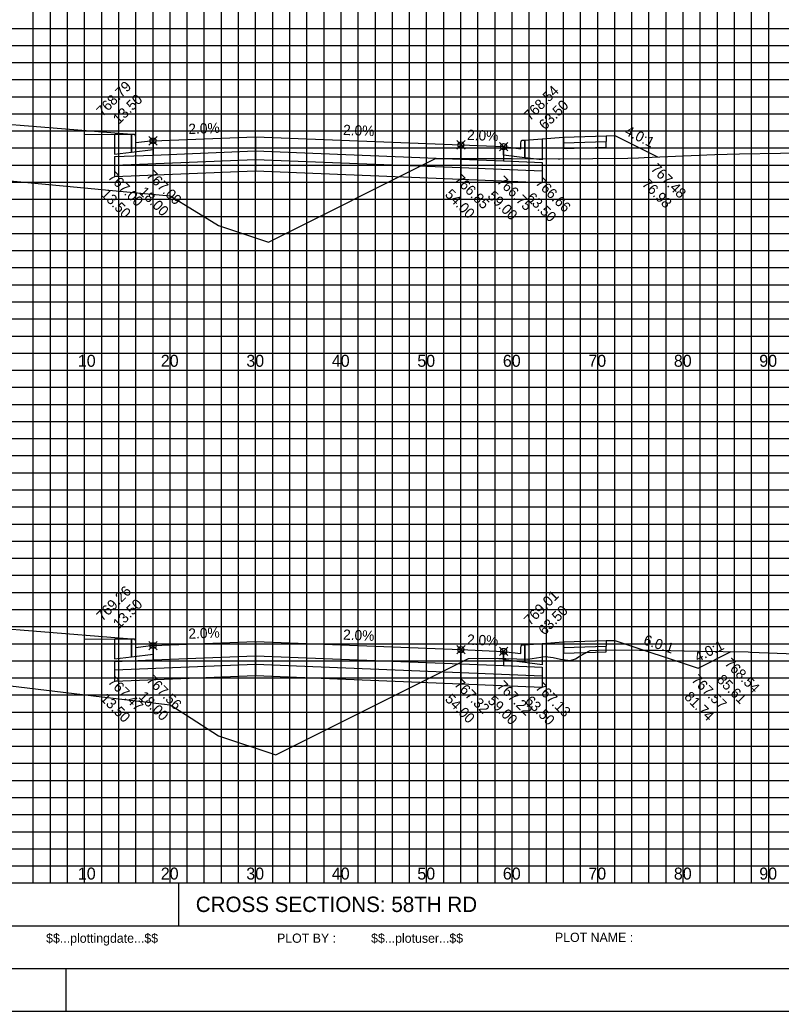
# Model space of a CAD drawing. Extents: x 578243 to 601557, y 174899 to 175559.
# Drawn here: x 600022.3 to 600111.3, y 174898.8 to 175014.8 of the extents above; entities that cross this region are included whole.
import ezdxf

# ---------------------------------------------------------------- set-up
doc = ezdxf.new("R2010")
doc.units = 0
for name, color, linetype in [('E_PROF_Grid', 7, 'Continuous'), ('E_PROF_GridMin', 7, 'Continuous'), ('P_CRDR_Label', 7, 'Continuous'), ('P_CRDR_Link', 7, 'Continuous'), ('P_E_XS_Ground', 7, 'Continuous'), ('P_XS_Text', 7, 'Continuous'), ('PLT_Sheet_Border', 7, 'Continuous'), ('PLT_Sheet_Info', 7, 'Continuous')]:
    doc.layers.add(name, color=color, linetype=linetype)

msp = doc.modelspace()

# ---------------------------------------------------------------- linework, layer by layer
at = {"layer": 'E_PROF_Grid'}
for p, q in [((600029.84, 174913.8), (600029.84, 175108.8)), ((600039.84, 174913.8), (600039.84, 175108.8)), ((600049.84, 174913.8), (600049.84, 175108.8)), ((600059.84, 174913.8), (600059.84, 175108.8)), ((600069.84, 174913.8), (600069.84, 175108.8)), ((600079.84, 174913.8), (600079.84, 175108.8)), ((600089.84, 174913.8), (600089.84, 175108.8)), ((600099.84, 174913.8), (600099.84, 175108.8)), ((600109.84, 174913.8), (600109.84, 175108.8)), ((599869.84, 175013.8), (600184.84, 175013.8)), ((599869.84, 175003.8), (600184.84, 175003.8)), ((599869.84, 174993.8), (600184.84, 174993.8)), ((599869.84, 174983.8), (600184.84, 174983.8)), ((599869.84, 174973.8), (600184.84, 174973.8)), ((599869.84, 174963.8), (600184.84, 174963.8)), ((599869.84, 174953.8), (600184.84, 174953.8)), ((599869.84, 174943.8), (600184.84, 174943.8)), ((599869.84, 174933.8), (600184.84, 174933.8)), ((599869.84, 174923.8), (600184.84, 174923.8))]:
    msp.add_line(p, q, dxfattribs=at)
at = {"layer": 'E_PROF_GridMin'}
for p, q in [((600023.84, 174913.8), (600023.84, 175108.8)), ((600025.84, 174913.8), (600025.84, 175108.8)), ((600027.84, 174913.8), (600027.84, 175108.8)), ((600031.84, 174913.8), (600031.84, 175108.8)), ((600033.84, 174913.8), (600033.84, 175108.8)), ((600035.84, 174913.8), (600035.84, 175108.8)), ((600037.84, 174913.8), (600037.84, 175108.8)), ((600041.84, 174913.8), (600041.84, 175108.8)), ((600043.84, 174913.8), (600043.84, 175108.8)), ((600045.84, 174913.8), (600045.84, 175108.8)), ((600047.84, 174913.8), (600047.84, 175108.8)), ((600051.84, 174913.8), (600051.84, 175108.8)), ((600053.84, 174913.8), (600053.84, 175108.8)), ((600055.84, 174913.8), (600055.84, 175108.8)), ((600057.84, 174913.8), (600057.84, 175108.8)), ((600061.84, 174913.8), (600061.84, 175108.8)), ((600063.84, 174913.8), (600063.84, 175108.8)), ((600065.84, 174913.8), (600065.84, 175108.8)), ((600067.84, 174913.8), (600067.84, 175108.8)), ((600071.84, 174913.8), (600071.84, 175108.8)), ((600073.84, 174913.8), (600073.84, 175108.8)), ((600075.84, 174913.8), (600075.84, 175108.8)), ((600077.84, 174913.8), (600077.84, 175108.8)), ((600081.84, 174913.8), (600081.84, 175108.8)), ((600083.84, 174913.8), (600083.84, 175108.8)), ((600085.84, 174913.8), (600085.84, 175108.8)), ((600087.84, 174913.8), (600087.84, 175108.8)), ((600091.84, 174913.8), (600091.84, 175108.8)), ((600093.84, 174913.8), (600093.84, 175108.8)), ((600095.84, 174913.8), (600095.84, 175108.8)), ((600097.84, 174913.8), (600097.84, 175108.8)), ((600101.84, 174913.8), (600101.84, 175108.8)), ((600103.84, 174913.8), (600103.84, 175108.8)), ((600105.84, 174913.8), (600105.84, 175108.8)), ((600107.84, 174913.8), (600107.84, 175108.8)), ((599869.84, 175011.8), (600184.84, 175011.8)), ((599869.84, 175009.8), (600184.84, 175009.8)), ((599869.84, 175007.8), (600184.84, 175007.8)), ((599869.84, 175005.8), (600184.84, 175005.8)), ((599869.84, 175001.8), (600184.84, 175001.8)), ((599869.84, 174999.8), (600184.84, 174999.8)), ((599869.84, 174997.8), (600184.84, 174997.8)), ((599869.84, 174995.8), (600184.84, 174995.8)), ((599869.84, 174991.8), (600184.84, 174991.8)), ((599869.84, 174989.8), (600184.84, 174989.8)), ((599869.84, 174987.8), (600184.84, 174987.8)), ((599869.84, 174985.8), (600184.84, 174985.8)), ((599869.84, 174981.8), (600184.84, 174981.8)), ((599869.84, 174979.8), (600184.84, 174979.8)), ((599869.84, 174977.8), (600184.84, 174977.8)), ((599869.84, 174975.8), (600184.84, 174975.8)), ((599869.84, 174971.8), (600184.84, 174971.8)), ((599869.84, 174969.8), (600184.84, 174969.8)), ((599869.84, 174967.8), (600184.84, 174967.8)), ((599869.84, 174965.8), (600184.84, 174965.8)), ((599869.84, 174961.8), (600184.84, 174961.8)), ((599869.84, 174959.8), (600184.84, 174959.8)), ((599869.84, 174957.8), (600184.84, 174957.8)), ((599869.84, 174955.8), (600184.84, 174955.8)), ((599869.84, 174951.8), (600184.84, 174951.8)), ((599869.84, 174949.8), (600184.84, 174949.8)), ((599869.84, 174947.8), (600184.84, 174947.8)), ((599869.84, 174945.8), (600184.84, 174945.8)), ((599869.84, 174941.8), (600184.84, 174941.8)), ((599869.84, 174939.8), (600184.84, 174939.8)), ((599869.84, 174937.8), (600184.84, 174937.8)), ((599869.84, 174935.8), (600184.84, 174935.8)), ((599869.84, 174931.8), (600184.84, 174931.8)), ((599869.84, 174929.8), (600184.84, 174929.8)), ((599869.84, 174927.8), (600184.84, 174927.8)), ((599869.84, 174925.8), (600184.84, 174925.8)), ((599869.84, 174921.8), (600184.84, 174921.8)), ((599869.84, 174919.8), (600184.84, 174919.8)), ((599869.84, 174917.8), (600184.84, 174917.8)), ((599869.84, 174915.8), (600184.84, 174915.8))]:
    msp.add_line(p, q, dxfattribs=at)
at = {"layer": 'P_CRDR_Label'}
for points in [[(600037.35, 175000.15), (600038.34, 175001.14)], [(600037.35, 175001.14), (600038.34, 175000.15)], [(600073.35, 174999.67), (600074.34, 175000.66)], [(600073.35, 175000.66), (600074.34, 174999.67)], [(600078.35, 174999.47), (600079.34, 175000.46)], [(600078.35, 175000.46), (600079.34, 174999.47)], [(600037.35, 174941.08), (600038.34, 174942.07)], [(600037.35, 174942.07), (600038.34, 174941.08)], [(600073.35, 174940.6), (600074.34, 174941.59)], [(600073.35, 174941.59), (600074.34, 174940.6)], [(600078.35, 174940.4), (600079.34, 174941.39)], [(600078.35, 174941.39), (600079.34, 174940.4)]]:
    msp.add_lwpolyline(points, dxfattribs=at)
for centre in [(600037.84, 175000.64), (600073.84, 175000.16), (600078.84, 174999.96), (600037.84, 174941.58), (600073.84, 174941.1), (600078.84, 174940.9)]:
    msp.add_circle(centre, 0.35, dxfattribs=at)
at = {"layer": 'P_CRDR_Link'}
for points in [[(600035.34, 175001.39), (600019.84, 175002.63)], [(600035.34, 175001.39), (600019.84, 175002.63)], [(600033.34, 175001.38), (600029.84, 175001.35)], [(600033.34, 175001.38), (600029.84, 175001.35)], [(600035.34, 175001.39), (600033.34, 175001.38)], [(600033.34, 175001.38), (600033.34, 174999.08)], [(600033.34, 175001.38), (600033.34, 174999.08)], [(600033.34, 175001.38), (600033.34, 174999.08)], [(600035.66, 175001.39), (600035.34, 175001.39)], [(600035.66, 175001.39), (600035.34, 175001.39)], [(600035.34, 175001.39), (600035.34, 174999.33)], [(600035.34, 174999.33), (600035.34, 175001.39)], [(600035.74, 175001.35), (600035.66, 175001.39)], [(600035.74, 175001.35), (600035.66, 175001.39)], [(600035.8, 175001.23), (600035.74, 175001.35)], [(600035.8, 175001.23), (600035.74, 175001.35)], [(600035.83, 175001.07), (600035.8, 175001.23)], [(600035.83, 175001.07), (600035.8, 175001.23)], [(600037.84, 175000.64), (600049.84, 175001.12)], [(600049.84, 175001.12), (600049.84, 174999.46)], [(600049.84, 175001.12), (600073.84, 175000.16)], [(600049.84, 175001.12), (600049.84, 174999.46)], [(600085.84, 175001.07), (600090.84, 175001.22)], [(600085.84, 175001.07), (600090.84, 175001.22)], [(600090.84, 175001.22), (600091.84, 175001.25)], [(600090.84, 175001.22), (600091.84, 175001.25)], [(600090.84, 175001.22), (600090.84, 175000.56)], [(600091.84, 175001.25), (600096.83, 174998.76)], [(600091.84, 175001.25), (600096.83, 174998.76)], [(600035.84, 175000.39), (600035.83, 175001.07)], [(600035.84, 175000.39), (600035.83, 175001.07)], [(600037.84, 175000.64), (600035.84, 175000.39)], [(600037.84, 175000.64), (600035.84, 175000.39)], [(600037.84, 174999.64), (600037.84, 175000.64)], [(600037.84, 175000.64), (600037.84, 174998.98)], [(600073.84, 175000.16), (600073.84, 174998.5)], [(600073.84, 175000.16), (600078.84, 174999.96)], [(600073.84, 175000.16), (600073.84, 174998.5)], [(600078.84, 174999.96), (600078.84, 174998.3)], [(600078.84, 174999.96), (600080.84, 174999.71)], [(600078.84, 174999.96), (600080.84, 174999.71)], [(600078.84, 174998.96), (600078.84, 174999.96)], [(600080.84, 174999.71), (600080.86, 175000.39)], [(600080.84, 174999.71), (600080.86, 175000.39)], [(600080.86, 175000.39), (600080.88, 175000.55)], [(600080.86, 175000.39), (600080.88, 175000.55)], [(600080.88, 175000.55), (600080.94, 175000.67)], [(600080.88, 175000.55), (600080.94, 175000.67)], [(600080.94, 175000.67), (600081.02, 175000.71)], [(600080.94, 175000.67), (600081.02, 175000.71)], [(600081.02, 175000.71), (600081.34, 175000.71)], [(600081.02, 175000.71), (600081.34, 175000.71)], [(600081.34, 175000.71), (600083.34, 175000.87)], [(600081.34, 175000.71), (600081.34, 174998.65)], [(600081.34, 174998.65), (600081.34, 175000.71)], [(600083.34, 175000.87), (600085.84, 175001.07)], [(600083.34, 175000.87), (600085.84, 175001.07)], [(600083.34, 175000.87), (600083.34, 174998.4)], [(600083.34, 175000.87), (600083.34, 174998.4)], [(600083.34, 175000.87), (600083.34, 174998.4)], [(600085.84, 175001.07), (600085.85, 175000.41)], [(600085.85, 175000.41), (600090.84, 175000.56)], [(600085.85, 175000.41), (600085.85, 174999.74)], [(600090.83, 174999.89), (600090.84, 175000.56)], [(600033.34, 174999.08), (600035.34, 174999.33)], [(600033.34, 174998.8), (600037.84, 174998.98)], [(600033.34, 174998.8), (600033.34, 174997.8)], [(600035.34, 174999.33), (600037.84, 174999.64)], [(600035.34, 174999.33), (600037.84, 174999.64)], [(600037.84, 174998.98), (600049.84, 174999.46)], [(600049.84, 174999.46), (600049.84, 174998.46)], [(600049.84, 174999.46), (600073.84, 174998.5)], [(600049.84, 174999.46), (600049.84, 174998.46)], [(600081.34, 174998.65), (600078.84, 174998.96)], [(600081.34, 174998.65), (600078.84, 174998.96)], [(600085.85, 174999.74), (600090.83, 174999.89)], [(600033.34, 174997.8), (600049.84, 174998.46)], [(600033.34, 174997.8), (600033.34, 174996.46)], [(600049.84, 174998.46), (600049.84, 174997.12)], [(600049.84, 174998.46), (600073.84, 174997.5)], [(600049.84, 174998.46), (600049.84, 174997.12)], [(600073.84, 174998.5), (600073.84, 174997.5)], [(600073.84, 174998.5), (600078.84, 174998.3)], [(600073.84, 174998.5), (600073.84, 174997.5)], [(600078.84, 174998.3), (600083.34, 174998.12)], [(600083.34, 174998.4), (600081.34, 174998.65)], [(600083.34, 174998.12), (600083.34, 174997.12)], [(600033.34, 174996.46), (600049.84, 174997.12)], [(600049.84, 174997.12), (600073.84, 174996.16)], [(600073.84, 174997.5), (600073.84, 174996.16)], [(600073.84, 174997.5), (600083.34, 174997.12)], [(600073.84, 174997.5), (600073.84, 174996.16)], [(600083.34, 174997.12), (600083.34, 174995.78)], [(600073.84, 174996.16), (600083.34, 174995.78)], [(600035.34, 174942.33), (600019.84, 174943.57)], [(600035.34, 174942.33), (600019.84, 174943.57)], [(600033.34, 174942.31), (600029.84, 174942.28)], [(600033.34, 174942.31), (600029.84, 174942.28)], [(600035.34, 174942.33), (600033.34, 174942.31)], [(600033.34, 174942.31), (600033.34, 174940.02)], [(600033.34, 174942.31), (600033.34, 174940.02)], [(600033.34, 174942.31), (600033.34, 174940.02)], [(600035.66, 174942.33), (600035.34, 174942.33)], [(600035.66, 174942.33), (600035.34, 174942.33)], [(600035.34, 174942.33), (600035.34, 174940.27)], [(600035.34, 174940.27), (600035.34, 174942.33)], [(600035.74, 174942.29), (600035.66, 174942.33)], [(600035.74, 174942.29), (600035.66, 174942.33)], [(600035.8, 174942.17), (600035.74, 174942.29)], [(600035.8, 174942.17), (600035.74, 174942.29)], [(600035.83, 174942.01), (600035.8, 174942.17)], [(600035.83, 174942.01), (600035.8, 174942.17)], [(600035.84, 174941.33), (600035.83, 174942.01)], [(600035.84, 174941.33), (600035.83, 174942.01)], [(600037.84, 174941.58), (600049.84, 174942.06)], [(600049.84, 174942.06), (600049.84, 174940.39)], [(600049.84, 174942.06), (600073.84, 174941.1)], [(600049.84, 174942.06), (600049.84, 174940.39)], [(600083.34, 174941.81), (600085.84, 174942.01)], [(600083.34, 174941.81), (600085.84, 174942.01)], [(600085.84, 174942.01), (600090.84, 174942.16)], [(600085.84, 174942.01), (600090.84, 174942.16)], [(600085.84, 174942.01), (600085.85, 174941.34)], [(600090.84, 174942.16), (600091.84, 174942.19)], [(600090.84, 174942.16), (600091.84, 174942.19)], [(600090.84, 174942.16), (600090.84, 174941.49)], [(600091.84, 174942.19), (600101.58, 174938.94)], [(600091.84, 174942.19), (600101.58, 174938.94)], [(600037.84, 174941.58), (600035.84, 174941.33)], [(600037.84, 174941.58), (600035.84, 174941.33)], [(600037.84, 174940.58), (600037.84, 174941.58)], [(600037.84, 174941.58), (600037.84, 174939.91)], [(600073.84, 174941.1), (600073.84, 174939.43)], [(600073.84, 174941.1), (600078.84, 174940.9)], [(600073.84, 174941.1), (600073.84, 174939.43)], [(600078.84, 174940.9), (600078.84, 174939.23)], [(600078.84, 174940.9), (600080.84, 174940.65)], [(600078.84, 174940.9), (600080.84, 174940.65)], [(600078.84, 174939.9), (600078.84, 174940.9)], [(600080.84, 174940.65), (600080.86, 174941.33)], [(600080.84, 174940.65), (600080.86, 174941.33)], [(600080.86, 174941.33), (600080.88, 174941.49)], [(600080.86, 174941.33), (600080.88, 174941.49)], [(600080.88, 174941.49), (600080.94, 174941.61)], [(600080.88, 174941.49), (600080.94, 174941.61)], [(600080.94, 174941.61), (600081.02, 174941.65)], [(600080.94, 174941.61), (600081.02, 174941.65)], [(600081.02, 174941.65), (600081.34, 174941.65)], [(600081.02, 174941.65), (600081.34, 174941.65)], [(600081.34, 174941.65), (600083.34, 174941.81)], [(600081.34, 174941.65), (600081.34, 174939.59)], [(600081.34, 174939.59), (600081.34, 174941.65)], [(600083.34, 174941.81), (600083.34, 174939.34)], [(600083.34, 174941.81), (600083.34, 174939.34)], [(600083.34, 174941.81), (600083.34, 174939.34)], [(600085.85, 174941.34), (600090.84, 174941.49)], [(600085.85, 174941.34), (600085.85, 174940.68)], [(600085.85, 174940.68), (600090.83, 174940.83)], [(600090.83, 174940.83), (600090.84, 174941.49)], [(600101.58, 174938.94), (600105.45, 174940.88)], [(600101.58, 174938.94), (600105.45, 174940.88)], [(600033.34, 174940.02), (600035.34, 174940.27)], [(600033.34, 174939.73), (600037.84, 174939.91)], [(600033.34, 174939.73), (600033.34, 174938.73)], [(600035.34, 174940.27), (600037.84, 174940.58)], [(600035.34, 174940.27), (600037.84, 174940.58)], [(600037.84, 174939.91), (600049.84, 174940.39)], [(600049.84, 174940.39), (600049.84, 174939.39)], [(600049.84, 174940.39), (600073.84, 174939.43)], [(600049.84, 174940.39), (600049.84, 174939.39)], [(600081.34, 174939.59), (600078.84, 174939.9)], [(600081.34, 174939.59), (600078.84, 174939.9)], [(600033.34, 174938.73), (600049.84, 174939.39)], [(600033.34, 174938.73), (600033.34, 174937.4)], [(600049.84, 174939.39), (600049.84, 174938.06)], [(600049.84, 174939.39), (600073.84, 174938.43)], [(600049.84, 174939.39), (600049.84, 174938.06)], [(600073.84, 174939.43), (600073.84, 174938.43)], [(600073.84, 174939.43), (600078.84, 174939.23)], [(600073.84, 174939.43), (600073.84, 174938.43)], [(600078.84, 174939.23), (600083.34, 174939.05)], [(600083.34, 174939.34), (600081.34, 174939.59)], [(600083.34, 174939.05), (600083.34, 174938.05)], [(600033.34, 174937.4), (600049.84, 174938.06)], [(600049.84, 174938.06), (600073.84, 174937.1)], [(600073.84, 174938.43), (600073.84, 174937.1)], [(600073.84, 174938.43), (600083.34, 174938.05)], [(600073.84, 174938.43), (600073.84, 174937.1)], [(600083.34, 174938.05), (600083.34, 174936.72)], [(600073.84, 174937.1), (600083.34, 174936.72)]]:
    msp.add_lwpolyline(points, dxfattribs=at)
at = {"layer": 'P_E_XS_Ground'}
for points in [[(600019.84, 174996.07), (600031.84, 174994.94), (600036.84, 174994.47), (600039.84, 174994.19), (600041.62, 174993.11), (600045.48, 174990.75), (600051.34, 174988.8), (600070.88, 174998.57), (600079.73, 174998.59), (600085.21, 174998.52), (600085.45, 174998.55), (600089.27, 174998.56), (600093.36, 174998.6), (600094.6, 174998.66), (600095.29, 174998.69), (600103.56, 174999.05), (600106.42, 174999.1), (600111.23, 174999.19), (600117.66, 174999.37)], [(600019.84, 174937.03), (600031.84, 174935.59), (600036.84, 174934.99), (600039.84, 174934.63), (600041.62, 174933.5), (600045.48, 174931.03), (600052.19, 174928.8), (600074.75, 174940.08), (600078.12, 174940.1), (600078.29, 174940.08), (600079.1, 174940.07), (600081.66, 174939.98), (600083.69, 174940.29), (600084.64, 174940.19), (600085.51, 174939.97), (600086.61, 174939.85), (600087.24, 174940.01), (600087.54, 174940.21), (600087.73, 174940.35), (600088.97, 174941), (600089.93, 174941.05), (600091.95, 174941.07), (600094.72, 174941.04), (600095.78, 174941.04), (600096.84, 174941.05), (600101.53, 174940.94), (600101.57, 174940.94), (600107.42, 174940.85), (600107.69, 174940.82), (600113.97, 174940.58)]]:
    msp.add_lwpolyline(points, dxfattribs=at)
at = {"layer": 'PLT_Sheet_Border'}
for points in [[(599857.19, 174898.8), (600197.19, 174898.8), (600197.19, 175118.8), (599857.19, 175118.8)], [(599859.59, 174903.8), (600190.59, 174903.8), (600190.59, 175113.8), (599859.59, 175113.8)]]:
    msp.add_lwpolyline(points, close=True, dxfattribs=at)
at = {"layer": 'PLT_Sheet_Info'}
for p, q in [((599869.84, 174913.8), (600184.84, 174913.8)), ((600040.84, 174908.8), (600040.84, 174913.8)), ((599869.84, 174908.8), (600184.84, 174908.8)), ((600027.69, 174898.8), (600027.69, 174903.8)), ((600022.69, 174898.8), (600032.69, 174898.8))]:
    msp.add_line(p, q, dxfattribs=at)

# ---------------------------------------------------------------- texts
at = {"layer": 'P_CRDR_Label'}
for s, rotation, p in [('768.79', 45, (600031.93, 175003.42)), ('768.54', 45, (600081.93, 175002.91)), ('13.50', 45, (600033.87, 175002.53)), ('63.50', 45, (600083.69, 175001.85)), ('2.0%', 2.2906, (600042, 175001.43)), ('2.0%', 357.7094, (600060.05, 175001.33)), ('4.0:1', 333.4349, (600092.91, 175001.41)), ('2.0%', 357.7094, (600074.55, 175000.75)), ('767.48', 315, (600095.98, 174997.28)), ('767.48', 315, (600095.98, 174997.28)), ('767.00', 315, (600032.49, 174996.32)), ('767.09', 315, (600036.99, 174996.5)), ('766.85', 315, (600072.99, 174996.02)), ('766.75', 315, (600077.99, 174995.82)), ('766.66', 315, (600082.49, 174995.64)), ('76.98', 315, (600094.94, 174995.49)), ('76.98', 315, (600094.94, 174995.49)), ('13.50', 315, (600031.67, 174994.31)), ('18.00', 315, (600036.11, 174994.56)), ('54.00', 315, (600071.9, 174994.28)), ('59.00', 315, (600076.89, 174994.09)), ('63.50', 315, (600081.43, 174993.88)), ('769.26', 45, (600031.93, 174944.36)), ('769.01', 45, (600081.93, 174943.85)), ('13.50', 45, (600033.87, 174943.47)), ('63.50', 45, (600083.62, 174942.71)), ('2.0%', 2.2906, (600042, 174942.37)), ('2.0%', 357.7094, (600060.05, 174942.27)), ('2.0%', 357.7094, (600074.55, 174941.69)), ('6.0:1', 341.5651, (600095.11, 174941.75)), ('4.0:1', 26.5651, (600101.54, 174939.62)), ('768.54', 315, (600104.6, 174939.4)), ('768.54', 315, (600104.6, 174939.4)), ('767.47', 315, (600032.49, 174937.26)), ('767.56', 315, (600036.99, 174937.44)), ('767.32', 315, (600072.99, 174936.96)), ('767.22', 315, (600077.99, 174936.76)), ('767.13', 315, (600082.49, 174936.58)), ('767.57', 315, (600100.73, 174937.47)), ('85.61', 315, (600103.68, 174937.49)), ('85.61', 315, (600103.68, 174937.49)), ('18.00', 315, (600036.08, 174935.52)), ('81.74', 315, (600099.88, 174935.49)), ('13.50', 315, (600031.61, 174935.31)), ('54.00', 315, (600071.9, 174935.22)), ('59.00', 315, (600076.89, 174935.03)), ('63.50', 315, (600081.25, 174934.99))]:
    msp.add_text(s, height=1.2, rotation=rotation, dxfattribs=at).set_placement(p)
at = {"layer": 'P_XS_Text'}
for s, p in [('10', (600029.05, 174974.2)), ('20', (600038.75, 174974.2)), ('30', (600048.75, 174974.2)), ('40', (600058.75, 174974.2)), ('50', (600068.75, 174974.2)), ('60', (600078.75, 174974.2)), ('70', (600088.75, 174974.2)), ('80', (600098.75, 174974.2)), ('90', (600108.74, 174974.2)), ('10', (600029.05, 174914.2)), ('20', (600038.75, 174914.2)), ('30', (600048.75, 174914.2)), ('40', (600058.75, 174914.2)), ('50', (600068.75, 174914.2)), ('60', (600078.75, 174914.2)), ('70', (600088.75, 174914.2)), ('80', (600098.75, 174914.2)), ('90', (600108.74, 174914.2))]:
    msp.add_text(s, height=1.4, rotation=360, dxfattribs=at).set_placement(p)
at = {"layer": 'PLT_Sheet_Info'}
for s, height, p in [('CROSS SECTIONS: 58TH RD                           ', 1.8, (600042.84, 174910.4)), ('PLOT NAME :                      ', 1.08, (600084.84, 174906.9))]:
    msp.add_text(s, height=height, dxfattribs=at).set_placement(p)
for s, p in [('$$...plottingdate...$$', (600025.34, 174906.8)), ('PLOT BY :', (600052.34, 174906.8)), ('$$...plotuser...$$', (600063.34, 174906.8))]:
    msp.add_text(s, height=1.08, rotation=360, dxfattribs=at).set_placement(p)

doc.saveas('drawing.dxf')
